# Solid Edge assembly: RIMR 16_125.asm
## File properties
Title: Zylinder
Author: ahadarics
Template: iso metric assembly.asm
Last saved by: ahadarics
Revision: 9
Application: Solid Edge
Username: ahadarics
Dokumentum tartalom típus: 1
Document Number: RIMR 16/125
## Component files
Profilrohr.par
Kolbenstange.par
Kit_1.par
Kit_2.par
Mutter_1.par
Mutter_2.par
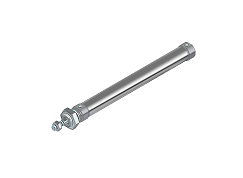
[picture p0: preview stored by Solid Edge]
